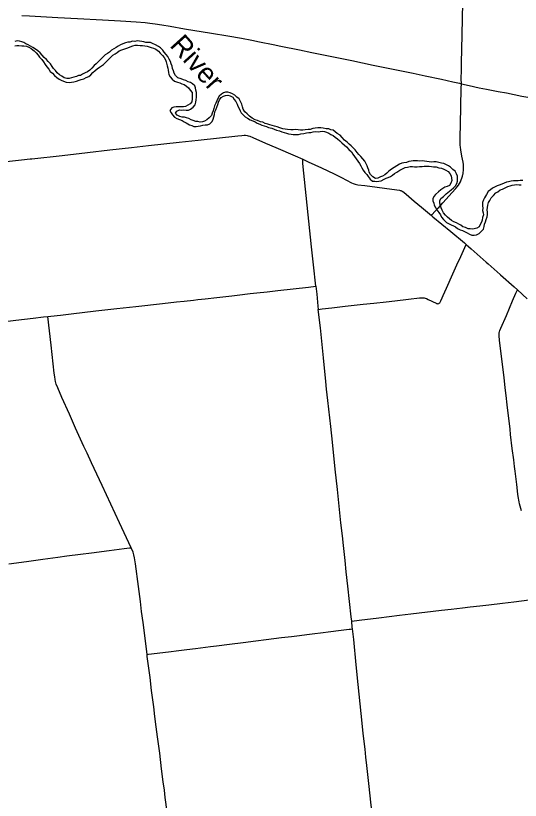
# Model space of a CAD drawing. Extents: x 0 to 680, y 0 to 440.
# Drawn here: x 248.2 to 332.1, y 233.7 to 364.2 of the extents above; entities that cross this region are included whole.
import ezdxf

# ---------------------------------------------------------------- set-up
doc = ezdxf.new("R2010")
doc.units = 0
for name, color, linetype in [('GM_X_County_Road', 7, 'Continuous'), ('GM_X_Major_River', 7, 'Continuous'), ('GM_X_Major_River_Text', 7, 'Continuous'), ('GM_X_Township_Road', 7, 'Continuous')]:
    doc.layers.add(name, color=color, linetype=linetype)

msp = doc.modelspace()

# ---------------------------------------------------------------- linework, layer by layer
at = {"layer": 'GM_X_County_Road'}
for points in [[(249.22, 364.22), (250.53, 364.15), (255.22, 363.89), (258.5, 363.7), (262.65, 363.48), (265.6, 363.31), (268.22, 363.15), (269.75, 363.04), (270.52, 362.97), (271.38, 362.85), (272.47, 362.68), (273.87, 362.44), (276.24, 362.02), (280.77, 361.27), (283.47, 360.82), (285.73, 360.43), (287.46, 360.12), (288.75, 359.87), (291, 359.4), (292.28, 359.13), (295.39, 358.49), (297.42, 358.08), (298.82, 357.8), (302.14, 357.11), (304.07, 356.72), (307.61, 355.99), (309.53, 355.58), (312.32, 355.01), (314.25, 354.61), (316.28, 354.18), (318.96, 353.61), (320.88, 353.19), (321.95, 352.95), (322.27, 352.88)], [(318.51, 332.32), (319.18, 333.06), (320.73, 334.77), (321.31, 335.41), (321.59, 335.75), (321.78, 336.01), (321.96, 336.29), (322.11, 336.57), (322.25, 336.87), (322.37, 337.17), (322.47, 337.48), (322.54, 337.8), (322.56, 337.9), (322.6, 338.12), (322.64, 338.45), (322.65, 338.77), (322.65, 339.1), (322.62, 339.42), (322.56, 339.85), (322.38, 340.82), (322.19, 341.9), (322.12, 342.33), (322.09, 342.66), (322.08, 342.99), (322.09, 343.76), (322.19, 348.9), (322.26, 352.29), (322.27, 352.72), (322.27, 352.88)], [(322.27, 352.88), (323.55, 352.58), (325.26, 352.22), (326.44, 351.99), (328.37, 351.6), (329.77, 351.34), (332.35, 350.83), (333.63, 350.57), (334.28, 350.46), (334.71, 350.41), (335.14, 350.37), (335.8, 350.35), (337.66, 350.33), (338.75, 350.31), (339.3, 350.28), (339.58, 350.25)], [(250.6, 340.37), (250.91, 340.41), (255.91, 340.97), (260.15, 341.45), (263.84, 341.87), (267.43, 342.26), (270.26, 342.59), (275.37, 343.14), (278.52, 343.49), (285.14, 344.23), (285.77, 344.29), (286.16, 344.32), (286.39, 344.31), (286.65, 344.28), (286.86, 344.23), (287.12, 344.16), (287.63, 343.96), (289.73, 343.02), (291.43, 342.28), (294.64, 340.87), (295.92, 340.31)], [(223.55, 337.4), (223.83, 337.44), (225.46, 337.64), (230.35, 338.19), (237.96, 339.02), (244.06, 339.65), (249.17, 340.21), (250.6, 340.37)], [(295.92, 340.31), (296.84, 339.9), (299.03, 338.89), (301.11, 337.92), (302.38, 337.29), (304.02, 336.41), (304.32, 336.28), (304.63, 336.18), (305.05, 336.09), (306.24, 335.94), (311.56, 335.25), (311.99, 335.17), (312.11, 335.14), (312.23, 335.1), (312.32, 335.06), (312.41, 335.01), (312.69, 334.83), (313.53, 334.13), (314.45, 333.36), (315.63, 332.38), (317.31, 330.98)], [(317.31, 330.98), (317.43, 331.11), (318.37, 332.17), (318.51, 332.32)], [(317.31, 330.98), (317.56, 330.76), (320.51, 328.33), (322.78, 326.44), (323.09, 326.17)], [(323.09, 326.17), (323.93, 325.43), (326.38, 323.23), (326.72, 322.93)], [(326.72, 322.93), (328.75, 321.13), (328.8, 321.08)], [(328.8, 321.08), (331.04, 319.09), (331.6, 318.59)], [(331.6, 318.59), (333.23, 317.12)], [(226.87, 311.05), (229.8, 311.41), (230.34, 311.47), (230.88, 311.53), (231.97, 311.67), (235.22, 312.06), (237.37, 312.32), (240.87, 312.73), (242.94, 312.96), (244.68, 313.16), (246.41, 313.36), (247.34, 313.46), (248.26, 313.57), (251.09, 313.89), (252.82, 314.1), (253.56, 314.18)], [(267.4, 275.73), (265.47, 279.85), (264.74, 281.44), (262.56, 286.09), (260.8, 289.86), (260.07, 291.45), (259.56, 292.54), (258.16, 295.63), (257.14, 297.93), (255.89, 300.73), (255.19, 302.33), (254.96, 302.94), (254.83, 303.35), (254.76, 303.67), (254.69, 304.15), (254.62, 304.76), (254.1, 309.43), (253.56, 314.18)], [(247.07, 273.06), (249.99, 273.45), (251.19, 273.6), (252.7, 273.81), (255.19, 274.15), (256.71, 274.35), (258.99, 274.64), (260.83, 274.88), (263.75, 275.26), (266.25, 275.58), (267.11, 275.69), (267.22, 275.7), (267.4, 275.73)], [(270.04, 257.99), (269.76, 260.25), (269.37, 263.29), (269.14, 265.13), (268.93, 266.76), (268.61, 269.26), (268.11, 273.05), (267.98, 274.03), (267.86, 274.57), (267.8, 274.76), (267.73, 274.98), (267.42, 275.69), (267.4, 275.73)], [(304.05, 263.53), (305.27, 263.68), (308.54, 264.07), (312.01, 264.5), (313.86, 264.72), (318.96, 265.32), (320.59, 265.52), (322.44, 265.74), (323.74, 265.89), (325.33, 266.07), (326.86, 266.25), (329.13, 266.52), (331.02, 266.75), (333.53, 267.05), (334.83, 267.21), (336.42, 267.4)], [(270.04, 257.99), (270.3, 258.02), (273.61, 258.43), (275.3, 258.64), (276.63, 258.8), (278.08, 258.98), (280.59, 259.3), (281.57, 259.42), (283.76, 259.68), (286.02, 259.95), (288.14, 260.23), (289.84, 260.45), (292.38, 260.77), (294.06, 260.99), (295.38, 261.15), (296.59, 261.3), (297.9, 261.46), (298.87, 261.57), (300.58, 261.79), (301.88, 261.95), (303.61, 262.16), (303.86, 262.2), (304.18, 262.24)], [(304.18, 262.24), (304.15, 262.5), (304.13, 262.71), (304.12, 262.87), (304.09, 263.15), (304.05, 263.53)], [(273.4, 231.71), (273.38, 231.82), (273.35, 232.04), (273.22, 233.02), (273.07, 234.21), (272.92, 235.4), (272.74, 236.81), (272.46, 238.98), (272.14, 241.59), (271.79, 244.3), (271.58, 245.93), (271.36, 247.66), (271.15, 249.29), (270.8, 252), (270.53, 254.17), (270.08, 257.65), (270.04, 257.99)]]:
    msp.add_lwpolyline(points, dxfattribs=at)
at = {"layer": 'GM_X_Major_River'}
for points in [[(272.67, 358.46), (272.3, 358.82), (271.93, 359.06), (271.47, 359.33), (270.95, 359.58), (270.61, 359.73), (270.21, 359.73), (269.86, 359.73), (269.5, 359.82), (269.16, 359.88), (268.76, 359.98), (268.37, 360), (268.01, 359.92), (267.62, 359.96), (267.18, 359.8), (266.83, 359.78), (266.46, 359.68), (266, 359.49), (265.6, 359.35), (265.23, 359.11), (264.88, 358.88), (264.54, 358.66), (264.15, 358.44), (263.79, 358.15), (263.45, 357.91), (263.06, 357.68), (262.68, 357.32), (262.38, 356.97), (261.99, 356.6), (261.59, 356.21), (261.25, 355.89), (260.89, 355.48), (260.51, 355.15), (260.14, 354.84), (259.77, 354.67), (259.31, 354.44), (258.96, 354.27), (258.62, 354.22), (258.29, 354.1), (257.86, 353.97), (257.5, 353.84), (257.09, 353.77), (256.71, 353.73), (256.28, 353.87), (255.87, 354.12), (255.5, 354.33), (255.12, 354.71), (254.85, 355.07), (254.52, 355.43), (254.28, 355.77), (253.98, 356.16), (253.6, 356.55), (253.34, 356.9), (252.96, 357.24), (252.61, 357.65), (252.25, 358.02), (251.88, 358.32), (251.51, 358.6), (251.08, 358.92), (250.68, 359.14), (250.31, 359.36), (249.9, 359.51), (249.56, 359.73), (249.21, 359.83), (248.83, 359.95), (248.47, 359.99), (248.05, 359.89)], [(248.05, 359.17), (248.4, 359.24), (248.73, 359.26), (249.21, 359.2), (249.59, 359.18), (249.99, 359.11), (250.38, 358.96), (250.8, 358.74), (251.26, 358.37), (251.61, 358.01), (251.95, 357.62), (252.19, 357.28), (252.54, 356.89), (252.83, 356.52), (253.13, 356.08), (253.41, 355.67), (253.69, 355.29), (253.96, 354.89), (254.31, 354.63), (254.65, 354.24), (255.04, 353.91), (255.41, 353.62), (255.76, 353.48), (256.13, 353.28), (256.59, 353.15), (257.07, 353.09), (257.49, 353.15), (257.87, 353.19), (258.3, 353.32), (258.76, 353.46), (259.09, 353.6), (259.52, 353.71), (259.93, 353.91), (260.34, 354.1), (260.7, 354.38), (261.04, 354.76), (261.4, 355.1), (261.77, 355.37), (262.12, 355.64), (262.47, 355.87), (262.81, 356.09), (263.21, 356.49), (263.61, 356.91), (264, 357.28), (264.38, 357.62), (264.72, 357.85), (265.05, 358.06), (265.41, 358.32), (265.84, 358.54), (266.17, 358.62), (266.84, 358.82), (267.26, 359.01), (267.68, 359.19), (268.06, 359.28), (268.47, 359.31), (268.9, 359.25), (269.3, 359.21), (269.66, 359.2), (270.04, 359.13), (270.4, 359.04), (270.75, 358.89), (271.13, 358.78), (271.52, 358.65), (271.92, 358.28), (272.21, 357.94), (272.58, 357.58), (272.88, 357.22), (273.12, 356.87), (273.21, 356.52), (273.39, 355.85), (273.48, 355.49), (273.54, 355.15), (273.61, 354.73), (273.68, 354.39), (273.89, 354.01), (274.23, 353.65), (274.6, 353.33), (275.08, 353.12), (275.46, 353), (275.81, 352.88), (276.19, 352.73), (276.6, 352.46), (276.95, 352.2), (277.21, 351.81), (277.52, 351.4), (277.55, 351.05), (277.56, 350.7), (277.56, 350.37), (277.47, 349.88), (277.18, 349.52), (276.79, 349.29), (276.43, 349.09), (276.07, 349.03), (275.25, 349.04), (274.86, 349.01), (274.5, 348.96), (274.17, 348.87), (273.83, 348.45), (274.02, 348.06)], [(297.15, 345.27), (296.82, 345.27), (296.32, 345.23), (295.92, 345.15), (295.56, 345.17), (295.13, 345.23), (294.72, 345.26), (294.33, 345.23), (293.92, 345.23), (293.4, 345.28), (293, 345.34), (292.6, 345.4), (292.1, 345.53), (291.64, 345.69), (291.22, 345.83), (290.85, 345.93), (290.46, 346.05), (290.1, 346.13), (289.65, 346.29), (289.29, 346.46), (288.88, 346.53), (288.38, 346.74), (287.99, 346.88), (287.53, 347.16), (287.04, 347.49), (286.69, 347.85), (286.28, 348.22), (286.03, 348.67), (285.89, 349.03), (285.77, 349.5), (285.59, 349.9), (285.34, 350.36), (284.98, 350.66), (284.62, 350.99), (284.26, 351.18), (283.83, 351.35), (283.44, 351.5), (283.1, 351.45), (282.73, 351.35), (282.39, 351.13), (282, 350.79), (281.79, 350.41), (281.62, 350.05), (281.47, 349.66), (281.25, 349.2), (281.12, 348.76), (281.01, 348.37), (280.85, 347.96), (280.73, 347.59), (280.39, 347.21), (280, 346.89), (279.59, 346.65), (279.26, 346.54), (278.87, 346.51), (278.5, 346.57), (278.12, 346.62), (277.72, 346.76), (277.35, 346.9), (277.01, 347.08), (276.62, 347.23), (276.25, 347.3), (275.89, 347.34), (275.51, 347.42), (275.07, 347.64), (274.79, 347.98), (275, 348.34), (275.43, 348.51), (275.78, 348.49), (276.18, 348.51), (276.54, 348.5), (276.93, 348.48), (277.26, 348.66), (277.72, 349), (278.01, 349.36), (278.14, 349.81), (278.18, 350.21), (278.27, 350.65), (278.28, 351.04), (278.27, 351.41), (278.15, 351.83), (278.07, 352.17), (277.97, 352.5), (277.61, 352.85), (277.24, 353.07), (276.9, 353.2), (276.46, 353.41), (276.09, 353.55), (275.69, 353.7), (275.18, 353.88), (274.74, 354.23), (274.52, 354.62), (274.44, 355.01), (274.29, 355.42), (274.19, 355.81), (274.07, 356.2), (273.92, 356.58), (273.7, 356.94), (273.48, 357.39), (273.22, 357.73), (272.9, 358.12), (272.67, 358.46)], [(274.02, 348.06), (274.26, 347.71), (274.62, 347.33), (274.98, 347.08), (275.42, 346.92), (275.86, 346.76), (276.2, 346.53), (276.56, 346.35), (277.11, 346.06), (277.46, 345.91), (277.83, 345.79), (278.18, 345.75), (278.54, 345.83), (278.91, 345.88), (279.33, 345.96), (279.7, 346.03), (280.1, 346.02), (280.49, 346.23), (280.86, 346.61), (281.03, 346.97), (281.15, 347.36), (281.25, 347.76), (281.33, 348.18), (281.48, 348.54), (281.63, 348.98), (281.8, 349.4), (281.91, 349.83), (282.07, 350.21), (282.34, 350.6), (282.76, 350.8), (283.09, 350.93), (283.45, 350.95), (283.88, 350.85), (284.28, 350.65), (284.52, 350.28), (284.8, 349.9), (285.03, 349.5), (285.13, 349.15), (285.34, 348.74), (285.52, 348.37), (285.7, 348.03), (286.03, 347.69), (286.37, 347.4), (286.74, 347.13), (287.2, 346.89), (287.63, 346.7), (288, 346.52), (288.34, 346.34), (288.78, 346.15), (289.14, 346.01), (289.48, 345.85), (289.91, 345.74), (290.25, 345.6), (290.75, 345.49), (291.16, 345.32), (291.58, 345.17), (292.05, 345.02), (292.46, 344.9), (292.82, 344.76), (293.19, 344.68), (293.55, 344.57), (293.97, 344.5), (294.33, 344.44), (294.76, 344.44), (295.23, 344.45), (295.62, 344.54), (296.1, 344.61), (296.55, 344.71), (296.93, 344.77), (297.26, 344.79), (297.62, 344.86), (298.08, 344.91), (298.45, 344.89), (298.79, 344.93), (299.16, 344.97), (299.51, 344.95), (299.88, 344.83), (300.24, 344.66), (300.59, 344.44), (300.95, 344.26), (301.31, 344), (301.68, 343.71), (302.06, 343.37), (302.43, 343.05), (302.83, 342.65), (303.18, 342.38), (303.6, 341.93), (304, 341.55), (304.24, 341.17), (304.51, 340.77), (304.81, 340.41), (305.06, 340.01), (305.32, 339.63), (305.57, 339.25), (305.74, 338.88), (305.98, 338.5), (306.22, 338.11), (306.56, 337.79), (306.79, 337.44), (307.11, 337.02), (307.53, 336.69)], [(325.42, 329.46), (325.24, 329.07), (324.86, 328.84), (324.42, 328.73), (324.07, 328.72), (323.73, 328.73), (323.38, 328.77), (322.96, 328.97), (322.54, 329.09), (322.19, 329.34), (321.84, 329.53), (321.49, 329.73), (321.05, 329.89), (320.64, 330.14), (320.3, 330.4), (319.95, 330.67), (319.64, 331.04), (319.32, 331.43), (319.08, 331.85), (318.92, 332.25), (318.78, 332.64), (318.68, 333.03), (318.7, 333.43), (318.88, 333.78), (319.3, 334.13), (319.75, 334.58), (320.59, 335.23), (320.99, 335.56), (321.32, 335.9), (321.53, 336.3), (321.64, 336.69), (321.63, 337.1), (321.63, 337.53), (321.45, 337.89), (321.23, 338.33), (320.87, 338.64), (320.49, 339.01), (320.15, 339.25), (319.71, 339.47), (319.34, 339.59), (318.99, 339.69), (318.51, 339.8), (318.06, 339.87), (317.71, 339.91), (317.29, 339.86), (316.93, 339.91), (316.54, 339.93), (316.14, 339.99), (315.75, 340.07), (315.37, 340.01), (314.99, 340.03), (314.59, 340.03), (314.26, 340.03), (313.92, 340.01), (313.54, 339.96), (313.13, 339.8), (312.71, 339.75), (312.36, 339.66), (312.02, 339.49), (311.54, 339.25), (311.08, 338.96), (310.66, 338.66), (310.23, 338.35), (309.89, 337.99), (309.54, 337.73), (309.16, 337.51), (308.82, 337.38), (308.41, 337.19), (307.98, 337.13), (307.57, 337.39), (307.17, 337.78), (306.97, 338.17), (306.89, 338.51), (306.71, 338.89), (306.6, 339.22), (306.43, 339.57), (306.21, 340), (305.89, 340.4), (305.57, 340.75), (305.23, 341.09), (304.98, 341.47), (304.65, 341.86), (304.3, 342.24), (303.95, 342.54), (303.61, 342.83), (303.27, 343.15), (302.86, 343.51), (302.44, 343.94), (302.13, 344.31), (301.66, 344.61), (301.32, 344.88), (300.95, 345.13), (300.59, 345.23), (300.25, 345.36), (299.8, 345.4), (299.33, 345.5), (298.93, 345.57), (298.42, 345.56), (298, 345.5), (297.58, 345.43), (297.15, 345.27)], [(307.53, 336.69), (307.88, 336.67), (308.22, 336.63), (308.58, 336.68), (308.95, 336.75), (309.42, 337.01), (309.77, 337.15), (310.1, 337.28), (310.48, 337.45), (310.83, 337.7), (311.19, 337.94), (311.55, 338.18), (312.07, 338.52), (312.49, 338.7), (312.91, 338.94), (313.35, 338.98), (313.76, 339.09), (314.14, 339.1), (314.51, 339.05), (314.92, 339.07), (315.31, 339.14), (315.75, 339.14), (316.1, 339.16), (316.51, 339.17), (316.9, 339.19), (317.31, 339.1), (317.67, 339.04), (318.09, 339.05), (318.51, 338.92), (318.96, 338.86), (319.38, 338.66), (319.72, 338.51), (320.06, 338.28), (320.37, 337.94), (320.56, 337.57), (320.66, 337.17), (320.68, 336.8), (320.53, 336.37), (320.28, 335.97), (319.92, 335.79), (319.53, 335.67), (319.19, 335.46), (318.85, 335.26), (318.47, 334.91), (317.97, 334.45), (317.71, 334.11), (317.56, 333.76), (317.53, 333.41), (317.68, 333.02), (317.78, 332.66), (317.95, 332.31), (318.22, 331.9), (318.51, 331.49), (318.8, 331.08), (318.95, 330.7), (319.31, 330.28), (319.83, 329.81), (320.23, 329.57), (320.59, 329.41), (320.97, 329.23), (321.32, 329.06), (321.66, 328.83), (322.07, 328.59), (322.44, 328.48), (322.82, 328.31), (323.24, 328.11), (323.63, 327.87), (324.03, 327.7), (324.42, 327.67), (324.78, 327.77), (325.25, 327.97), (325.64, 328.35), (325.95, 328.69), (326.04, 329.12), (326.1, 329.5), (326.29, 329.91), (326.42, 330.31), (326.54, 330.72), (326.6, 331.15), (326.61, 331.5), (326.59, 331.9), (326.6, 332.3), (326.67, 332.7), (326.79, 333.13), (326.99, 333.48), (327.23, 333.92), (327.61, 334.29), (328, 334.71), (328.34, 334.92), (328.74, 335.21), (329.12, 335.37), (329.66, 335.62), (330.02, 335.79), (330.37, 335.9), (330.71, 336.03), (331.11, 336.09), (331.48, 336.1), (331.87, 336.08), (332.23, 336.04)], [(332.47, 336.79), (332.05, 336.76), (331.72, 336.73), (331.33, 336.74), (330.96, 336.71), (330.54, 336.65), (330.13, 336.57), (329.75, 336.5), (329.38, 336.37), (329, 336.18), (328.57, 336.01), (328.22, 335.91), (327.87, 335.73), (327.45, 335.49), (327.12, 335.25), (326.75, 334.96), (326.46, 334.47), (326.13, 333.9), (325.95, 333.55), (325.8, 333.14), (325.76, 332.6), (325.86, 332.18), (325.8, 331.79), (325.89, 331.39), (325.93, 331.06), (325.79, 330.62), (325.71, 330.2), (325.63, 329.86), (325.42, 329.46)]]:
    msp.add_lwpolyline(points, dxfattribs=at)
at = {"layer": 'GM_X_Township_Road'}
for points in [[(322.27, 352.88), (322.26, 353.71), (322.29, 355.13), (322.31, 356.44), (322.36, 358.52), (322.46, 363.66), (322.5, 366.39), (322.55, 368.58), (322.57, 370.87), (322.59, 372.08), (322.61, 373.28), (322.69, 377), (322.74, 379.84), (322.78, 381.59), (322.88, 386.62), (322.9, 388.04), (322.93, 390.67), (322.97, 392.53), (323.02, 397.12), (323.05, 398.65), (323.08, 400.07), (323.09, 400.32)], [(298.1, 319.23), (297.72, 322.74), (297.39, 325.78), (295.95, 339.6), (295.93, 340.03), (295.92, 340.31)], [(298.5, 315.35), (299.14, 315.45), (300.77, 315.62), (302.94, 315.87), (305.98, 316.21), (307.72, 316.4), (309.78, 316.63), (311.2, 316.79), (313.48, 317.03), (315.32, 317.25), (315.65, 317.28), (315.86, 317.28), (316.07, 317.26), (316.28, 317.21), (316.49, 317.14), (316.78, 317), (318.06, 316.37), (318.17, 316.33), (318.28, 316.31), (318.39, 316.3), (318.51, 316.33), (318.61, 316.38), (318.69, 316.46), (318.76, 316.56), (318.85, 316.76), (319.07, 317.26), (319.25, 317.66), (319.79, 318.86), (320.87, 321.25), (321.54, 322.74), (322.16, 324.14), (322.83, 325.63), (322.98, 325.92), (323.09, 326.17)], [(253.56, 314.18), (254.05, 314.24), (255.68, 314.42), (257.42, 314.63), (261.55, 315.09), (263.5, 315.32), (265.02, 315.49), (268.18, 315.85), (272.63, 316.35), (274.91, 316.6), (276.22, 316.74), (277.74, 316.91), (278.5, 317), (279.7, 317.13), (281.65, 317.34), (284.15, 317.63), (285.02, 317.73), (287.19, 317.98), (288.28, 318.1), (290.02, 318.3), (291.76, 318.5), (296.86, 319.07), (298.1, 319.23)], [(298.1, 319.23), (298.23, 317.87), (298.42, 315.9), (298.5, 315.35)], [(332.28, 281.84), (331.96, 283), (331.88, 283.34), (331.81, 283.64), (331.76, 283.97), (331.68, 284.6), (331.6, 285.21), (331.48, 286.24), (331.32, 287.55), (331.22, 288.47), (331.12, 289.22), (330.97, 290.36), (330.74, 292.21), (330.46, 294.56), (330.37, 295.43), (329.91, 299.48), (329.71, 301.06), (329.56, 302.29), (329.37, 304.03), (329.1, 306.2), (328.64, 310.22), (328.57, 310.98), (328.55, 311.24), (328.57, 311.49), (328.59, 311.63), (328.65, 311.85), (328.81, 312.26), (329.75, 314.35), (330.77, 316.77), (331.34, 318.07), (331.49, 318.36), (331.6, 318.59)], [(304.05, 263.53), (303.96, 264.23), (303.4, 269.34), (303.14, 271.73), (302.94, 273.58), (302.68, 276.08), (302.5, 277.71), (302.26, 279.89), (302.02, 282.06), (301.67, 285.43), (301.32, 288.81), (300.85, 293.26), (300.56, 295.87), (300.09, 300.22), (299.88, 302.1), (299.76, 303.38), (299.36, 307.29), (298.85, 312.3), (298.5, 315.35)], [(304.18, 262.24), (304.15, 262.5), (304.13, 262.71), (304.12, 262.87), (304.09, 263.15), (304.05, 263.53)], [(308.32, 223.25), (308.31, 223.31), (308.22, 224.05), (307.83, 227.77), (307.39, 232.01), (307.23, 233.42), (306.95, 236.03), (306.57, 239.51), (306.42, 240.92), (306.3, 242.23), (305.98, 244.83), (305.78, 246.57), (305.14, 252.99), (304.8, 256.25), (304.38, 260.49), (304.18, 262.24)]]:
    msp.add_lwpolyline(points, dxfattribs=at)

# ---------------------------------------------------------------- texts
at = {"layer": 'GM_X_Major_River_Text'}
msp.add_text('River', height=3.335, rotation=312.0142, dxfattribs=at).set_placement((273.67, 359.17))

doc.saveas('drawing.dxf')
